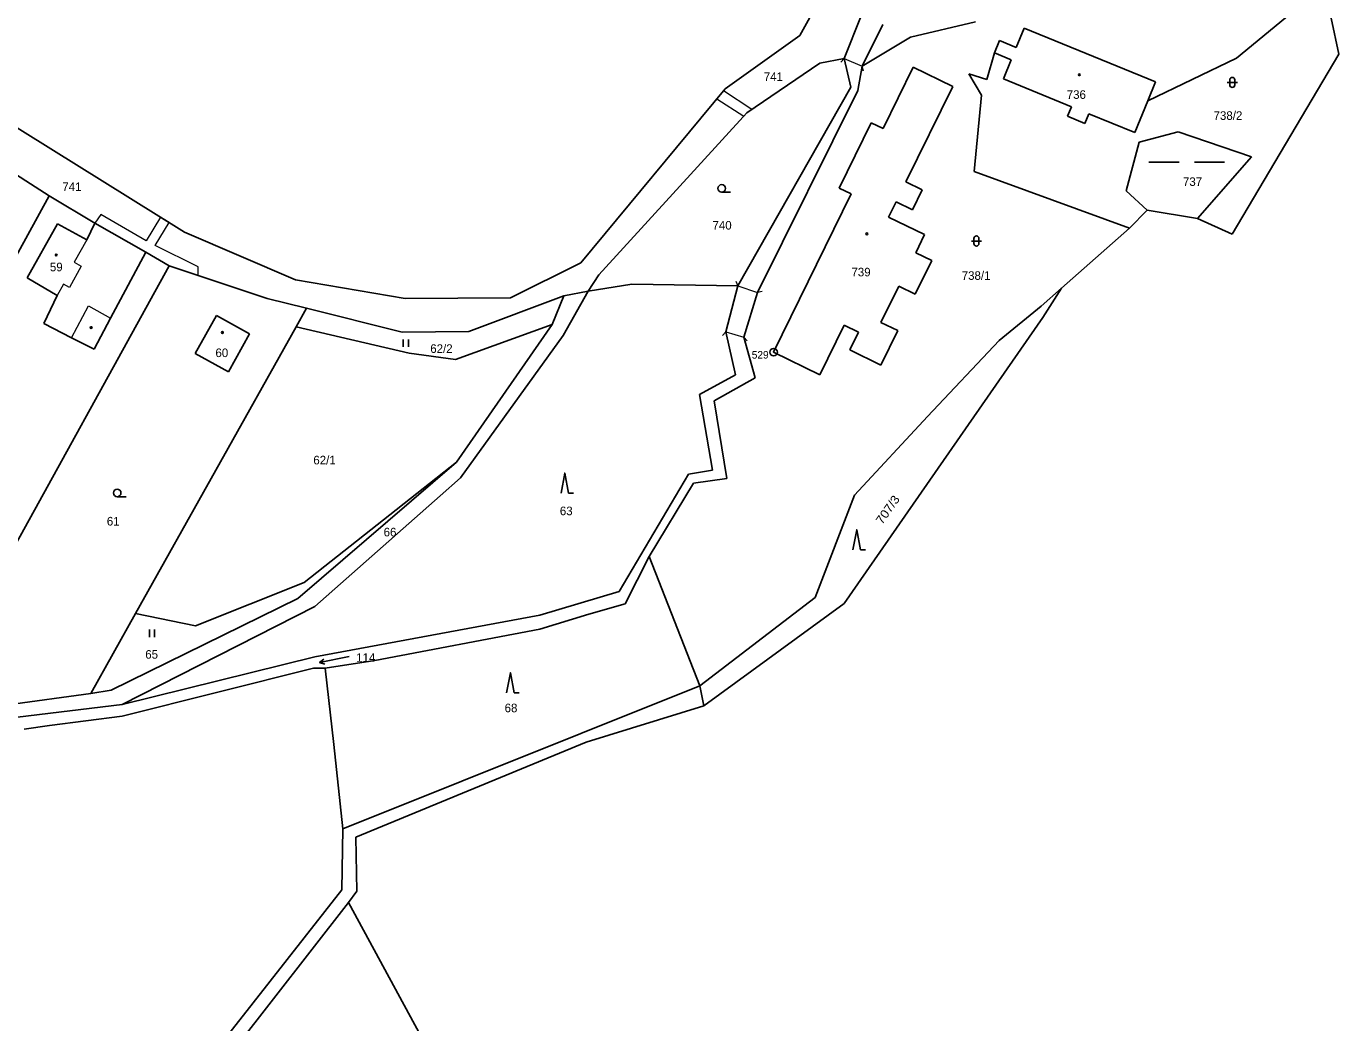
# Model space of a CAD drawing. Extents: x -727701 to -724405, y -960481 to -957284.
# Drawn here: x -726194 to -725934.2, y -958285.9 to -958088.6 of the extents above; entities that cross this region are included whole.
import ezdxf
from ezdxf.enums import TextEntityAlignment as Align

# ---------------------------------------------------------------- set-up
doc = ezdxf.new("R2010")
doc.units = 0
doc.header["$LTSCALE"] = 0.68
for name, color, linetype, lineweight in [('1', 7, 'Continuous', 25), ('13', 7, 'Continuous', 13), ('3', 7, 'Continuous', 25), ('4', 7, 'Continuous', 13), ('5', 7, 'Continuous', 25), ('8', 7, 'Continuous', 25)]:
    doc.layers.add(name, color=color, linetype=linetype, lineweight=lineweight)
doc.layers.add('2', color=7, linetype='Continuous')

msp = doc.modelspace()

# ---------------------------------------------------------------- linework, layer by layer
at = {"layer": '1'}
for p, q in [((-726036.81, -958083.12), (-726040.87, -958090.42)), ((-725942.48, -958085.07), (-725954.39, -958094.93)), ((-726028.71, -958086.53), (-726032.04, -958095.01)), ((-726006.06, -958087.73), (-726018.93, -958090.76)), ((-725935.63, -958086.98), (-725934.15, -958094.15)), ((-726024.39, -958088.24), (-726028.5, -958096.53)), ((-725997.99, -958092.81), (-725996.42, -958088.97)), ((-725996.42, -958088.97), (-725970.43, -958099.62)), ((-726040.87, -958090.42), (-726055.64, -958101.03)), ((-726018.93, -958090.76), (-726028.5, -958096.53)), ((-726002.27, -958093.89), (-726001.28, -958091.46)), ((-726001.28, -958091.46), (-725997.99, -958092.81)), ((-726032.04, -958095.01), (-726036.89, -958095.92)), ((-726032.04, -958095.01), (-726030.75, -958100.66)), ((-726002.27, -958093.89), (-726003.85, -958099.18)), ((-725998.99, -958095.24), (-726002.27, -958093.89)), ((-726000.53, -958099.02), (-725998.99, -958095.24)), ((-725954.39, -958094.93), (-725971.96, -958103.35)), ((-725934.15, -958094.15), (-725955.25, -958129.8)), ((-726036.89, -958095.92), (-726051.3, -958105.73)), ((-726028.5, -958096.53), (-726029.36, -958101.34)), ((-726024.36, -958108.87), (-726018.39, -958096.7)), ((-726018.39, -958096.7), (-726010.58, -958100.53)), ((-726003.85, -958099.18), (-726007.35, -958098.02)), ((-726007.35, -958098.02), (-726004.88, -958102.28)), ((-726030.75, -958100.66), (-726053.12, -958140)), ((-726010.58, -958100.53), (-726019.85, -958119.43)), ((-725987.05, -958104.54), (-726000.53, -958099.02)), ((-725970.43, -958099.62), (-725971.96, -958103.35)), ((-726206.6, -958101.98), (-726162.64, -958129.41)), ((-726055.64, -958101.03), (-726084.17, -958135.45)), ((-726029.36, -958101.34), (-726049.25, -958141.32)), ((-726004.88, -958102.28), (-726006.32, -958117.35)), ((-726051.3, -958105.73), (-726080.66, -958137.85)), ((-725987.82, -958106.43), (-725987.05, -958104.54)), ((-725983.61, -958105.93), (-725984.4, -958107.84)), ((-725974.54, -958109.65), (-725983.61, -958105.93)), ((-725971.96, -958103.35), (-725974.54, -958109.65)), ((-726212.67, -958107.28), (-726189.44, -958122.17)), ((-726033.04, -958120.65), (-726026.69, -958107.72)), ((-726026.69, -958107.72), (-726024.36, -958108.87)), ((-725984.4, -958107.84), (-725987.82, -958106.43)), ((-725973.63, -958111.53), (-725965.95, -958109.5)), ((-725965.95, -958109.5), (-725951.45, -958114.49)), ((-725976.24, -958121.22), (-725973.63, -958111.53)), ((-725951.45, -958114.49), (-725962.09, -958126.65)), ((-726006.32, -958117.35), (-725975.57, -958128.62)), ((-726030.7, -958121.79), (-726033.04, -958120.65)), ((-726019.85, -958119.43), (-726016.62, -958121.02)), ((-726016.62, -958121.02), (-726018.56, -958124.97)), ((-725972.05, -958125), (-725976.24, -958121.22)), ((-726189.44, -958122.17), (-726232.42, -958200.38)), ((-726189.44, -958122.17), (-726180.39, -958127.62)), ((-726046.03, -958153.14), (-726030.7, -958121.79)), ((-726021.79, -958123.38), (-726023.29, -958126.43)), ((-726018.56, -958124.97), (-726021.79, -958123.38)), ((-726023.29, -958126.43), (-726016.14, -958129.86)), ((-725972.05, -958125), (-725975.57, -958128.62)), ((-725962.09, -958126.65), (-725972.05, -958125)), ((-725955.25, -958129.8), (-725962.09, -958126.65)), ((-726193.78, -958138.44), (-726187.83, -958127.7)), ((-726187.83, -958127.7), (-726181.96, -958130.87)), ((-726181.96, -958130.87), (-726180.39, -958127.62)), ((-726180.39, -958127.62), (-726170.34, -958133.37)), ((-725975.57, -958128.62), (-725989.01, -958140.46)), ((-726140.67, -958138.85), (-726162.64, -958129.41)), ((-726016.14, -958129.86), (-726017.9, -958133.46)), ((-726177.3, -958146.43), (-726170.34, -958133.37)), ((-726170.34, -958133.37), (-726165.7, -958136.02)), ((-726017.9, -958133.46), (-726014.73, -958135.02)), ((-726165.7, -958136.02), (-726206.85, -958210.65)), ((-726165.7, -958136.02), (-726146.3, -958142.5)), ((-726084.17, -958135.45), (-726098.15, -958142.38)), ((-726014.73, -958135.02), (-726017.99, -958141.67)), ((-726118.97, -958142.54), (-726140.67, -958138.85)), ((-726080.66, -958137.85), (-726082.72, -958141.07)), ((-726082.72, -958141.07), (-726074.07, -958139.65)), ((-726053.12, -958140), (-726074.07, -958139.65)), ((-726106.38, -958149.08), (-726087.56, -958141.99)), ((-726089.89, -958147.63), (-726087.56, -958141.99)), ((-726082.72, -958141.07), (-726087.67, -958149.83)), ((-726087.56, -958141.99), (-726082.72, -958141.07)), ((-726053.12, -958140), (-726055.46, -958149.11)), ((-726049.25, -958141.32), (-726051.94, -958150.17)), ((-726021.26, -958140.06), (-726024.79, -958147.24)), ((-726017.99, -958141.67), (-726021.26, -958140.06)), ((-725989.01, -958140.46), (-725993.09, -958144.06)), ((-725992.76, -958146.28), (-725989.01, -958140.46)), ((-726146.3, -958142.5), (-726138.52, -958144.45)), ((-726140.58, -958148.13), (-726138.52, -958144.45)), ((-726138.52, -958144.45), (-726119.58, -958149.18)), ((-726098.15, -958142.38), (-726118.97, -958142.54)), ((-725993.09, -958144.06), (-726001.37, -958150.83)), ((-726190.53, -958147.44), (-726185.04, -958150.27)), ((-726180.57, -958152.56), (-726177.3, -958146.43)), ((-726160.52, -958153.38), (-726156.34, -958145.86)), ((-726156.34, -958145.86), (-726149.79, -958149.52)), ((-725992.76, -958146.28), (-726032.06, -958202.88)), ((-726024.79, -958147.24), (-726021.44, -958148.88)), ((-726172.34, -958204.88), (-726140.58, -958148.13)), ((-726149.79, -958149.52), (-726153.97, -958157.03)), ((-726140.58, -958148.13), (-726118.21, -958153.35)), ((-726119.58, -958149.18), (-726106.38, -958149.08)), ((-726109, -958154.58), (-726089.89, -958147.63)), ((-726108.8, -958174.9), (-726089.89, -958147.63)), ((-726087.67, -958149.83), (-726108, -958178)), ((-726053.6, -958157.6), (-726055.46, -958149.11)), ((-726032.09, -958147.77), (-726036.91, -958157.6)), ((-726029.21, -958149.18), (-726032.09, -958147.77)), ((-726030.93, -958152.68), (-726029.21, -958149.18)), ((-726021.44, -958148.88), (-726024.78, -958155.7)), ((-726185.04, -958150.27), (-726180.57, -958152.56)), ((-726051.94, -958150.17), (-726049.65, -958158.2)), ((-726024.78, -958155.7), (-726030.93, -958152.68)), ((-726001.37, -958150.83), (-726015.54, -958165.88)), ((-726153.97, -958157.03), (-726160.52, -958153.38)), ((-726118.21, -958153.35), (-726109, -958154.58)), ((-726036.91, -958157.6), (-726046.03, -958153.14)), ((-726060.7, -958161.55), (-726053.6, -958157.6)), ((-726049.65, -958158.2), (-726057.8, -958162.8)), ((-726058.12, -958176.52), (-726060.7, -958161.55)), ((-726057.8, -958162.8), (-726055.29, -958178.16)), ((-726015.54, -958165.88), (-726030.02, -958181.48)), ((-726140.2, -958201.9), (-726108.8, -958174.9)), ((-726138.99, -958198.75), (-726108.8, -958174.9)), ((-726108, -958178), (-726112.05, -958181.6)), ((-726076.6, -958200.5), (-726062.87, -958177.33)), ((-726062.87, -958177.33), (-726058.12, -958176.52)), ((-726055.29, -958178.16), (-726061.86, -958179.07)), ((-726061.86, -958179.07), (-726070.66, -958193.58)), ((-726112.05, -958181.6), (-726136.85, -958203.5)), ((-726030.02, -958181.48), (-726037.82, -958201.71)), ((-726070.66, -958193.58), (-726075.4, -958203)), ((-726070.66, -958193.58), (-726060.66, -958219.2)), ((-726160.5, -958207.3), (-726138.99, -958198.75)), ((-726177.2, -958220.1), (-726140.2, -958201.9)), ((-726092.3, -958205.2), (-726076.6, -958200.5)), ((-726037.82, -958201.71), (-726060.66, -958219.2)), ((-726136.85, -958203.5), (-726175, -958222.9)), ((-726075.4, -958203), (-726082.6, -958205)), ((-726059.85, -958223.18), (-726032.06, -958202.88)), ((-726181.2, -958220.7), (-726172.34, -958204.88)), ((-726172.34, -958204.88), (-726160.5, -958207.3)), ((-726136.85, -958213.5), (-726092.3, -958205.2)), ((-726082.6, -958205), (-726092.3, -958208)), ((-726092.3, -958208), (-726125, -958214.2)), ((-726175, -958222.9), (-726136.85, -958213.5)), ((-726125, -958214.2), (-726134.8, -958215.7)), ((-726137.1, -958215.7), (-726175, -958225.2)), ((-726134.8, -958215.7), (-726137.1, -958215.7)), ((-726133.1, -958230.8), (-726134.8, -958215.7)), ((-726181.2, -958220.7), (-726177.2, -958220.1)), ((-726131.32, -958247.51), (-726060.66, -958219.2)), ((-726060.66, -958219.2), (-726059.85, -958223.18)), ((-726197.6, -958223), (-726181.2, -958220.7)), ((-726195.7, -958225.4), (-726175, -958222.9)), ((-726175, -958225.2), (-726189.4, -958227.05)), ((-726083.14, -958230.39), (-726059.85, -958223.18)), ((-726189.4, -958227.05), (-726194.4, -958227.8)), ((-726128.76, -958249.16), (-726083.14, -958230.39)), ((-726131.32, -958247.51), (-726133.1, -958230.8)), ((-726131.48, -958259.62), (-726131.32, -958247.51)), ((-726128.53, -958259.86), (-726128.76, -958249.16)), ((-726156.53, -958291.46), (-726131.48, -958259.62)), ((-726130.22, -958262.09), (-726128.53, -958259.86)), ((-726130.22, -958262.09), (-726152.69, -958291.05)), ((-726107.42, -958304.01), (-726130.22, -958262.09))]:
    msp.add_line(p, q, dxfattribs=at)
msp.add_lwpolyline([(-726190.53, -958147.44), (-726187.88, -958141.93), (-726193.78, -958138.44)], dxfattribs=at)
at = {"layer": '13'}
for points in [[(-726057.24, -958102.96), (-726051.93, -958106.42), (-726051.3, -958105.73), (-726050.34, -958105.07), (-726055.96, -958101.41)], [(-726180.39, -958127.62), (-726170.34, -958133.37), (-726165.7, -958136.02), (-726159.98, -958137.93), (-726159.96, -958136.27), (-726168.48, -958132.04), (-726165.71, -958127.49), (-726167.41, -958126.44), (-726170.24, -958131.1), (-726179.2, -958125.88)]]:
    msp.add_lwpolyline(points, close=True, dxfattribs=at)
at = {"layer": '3'}
for p, q in [((-725956.221, -958099.731), (-725954.219, -958099.731)), ((-725955.721, -958099.231), (-725955.721, -958100.232)), ((-725954.719, -958100.232), (-725954.719, -958099.231)), ((-725971.739, -958115.51), (-725965.739, -958115.51)), ((-725962.739, -958115.51), (-725956.739, -958115.51)), ((-726056.303, -958121.46), (-726054.553, -958121.46)), ((-726006.881, -958131.131), (-726004.879, -958131.131)), ((-726006.381, -958130.631), (-726006.381, -958131.632)), ((-726005.379, -958131.632), (-726005.379, -958130.631)), ((-726119.341, -958152.1), (-726119.341, -958150.6)), ((-726118.34, -958152.1), (-726118.34, -958150.6)), ((-726086.62, -958181.08), (-726085.624, -958181.08)), ((-726175.983, -958181.77), (-726174.233, -958181.77)), ((-726028.83, -958192.29), (-726027.834, -958192.29)), ((-726169.571, -958209.55), (-726169.571, -958208.05)), ((-726168.57, -958209.55), (-726168.57, -958208.05)), ((-726135.903, -958214.619), (-726135.051, -958213.925)), ((-726097.4, -958220.62), (-726096.404, -958220.62))]:
    msp.add_line(p, q, dxfattribs=at)
for points in [[(-726086.62, -958181.08), (-726087.37, -958177.08), (-726088.12, -958181.08)], [(-726028.83, -958192.29), (-726029.58, -958188.29), (-726030.33, -958192.29)], [(-726130.034, -958213.371), (-726135.903, -958214.619), (-726134.843, -958214.906)], [(-726097.4, -958220.62), (-726098.15, -958216.62), (-726098.9, -958220.62)]]:
    msp.add_lwpolyline(points, dxfattribs=at)
for centre in [(-726056.3029, -958120.7098), (-726175.9829, -958181.0198)]:
    msp.add_circle(centre, 0.75, dxfattribs=at)
for centre, start, end in [((-725955.22, -958099.2309), 0, 180), ((-725955.22, -958100.2309), 180, 359.98789), ((-726005.88, -958130.6309), 0, 180), ((-726005.88, -958131.6309), 180, 359.98789)]:
    msp.add_arc(centre, 0.5, start, end, dxfattribs=at)
at = {"layer": '4'}
for p, q in [((-726032.748, -958095.717), (-726032.041, -958095.01)), ((-726032.04, -958095.01), (-726028.5, -958096.53)), ((-726028.242, -958097.496), (-726028.5, -958096.531)), ((-726181.96, -958130.87), (-726184.52, -958135.31)), ((-726183.14, -958136.14), (-726185.44, -958140.32)), ((-726184.52, -958135.31), (-726183.14, -958136.14)), ((-726186.64, -958139.67), (-726187.88, -958141.93)), ((-726185.44, -958140.32), (-726186.64, -958139.67)), ((-726053.494, -958139.072), (-726053.12, -958139.999)), ((-726053.12, -958140), (-726049.25, -958141.32)), ((-726048.271, -958141.113), (-726049.249, -958141.32)), ((-726185.04, -958150.27), (-726181.69, -958143.99)), ((-726181.69, -958143.99), (-726177.3, -958146.43)), ((-726056.168, -958149.817), (-726055.461, -958149.11)), ((-726055.46, -958149.11), (-726051.94, -958150.17)), ((-726051.284, -958150.925), (-726051.94, -958150.171))]:
    msp.add_line(p, q, dxfattribs=at)
at = {"layer": '5'}
for centre in [(-725985.5068, -958098.2092), (-726027.5668, -958129.7092), (-726188.0468, -958133.9092), (-726181.1368, -958148.2792), (-726155.1568, -958149.2392)]:
    msp.add_circle(centre, 0.175, dxfattribs=at)
at = {"layer": '8'}
for radius in [0.75, 0.03]:
    msp.add_circle((-726046.03, -958153.1398), radius, dxfattribs=at)

# ---------------------------------------------------------------- texts
at = {"layer": '2'}
for s, p in [('741', (-726047.97, -958099.435)), ('736', (-725988, -958102.985)), ('738/2', (-725958.93, -958107.145)), ('737', (-725964.99, -958120.225)), ('741', (-726186.85, -958121.235)), ('740', (-726058.13, -958128.865)), ('739', (-726030.62, -958138.135)), ('738/1', (-726008.79, -958138.825)), ('60', (-726156.53, -958154.115)), ('62/2', (-726114, -958153.285)), ('62/1', (-726137.15, -958175.365)), ('63', (-726088.35, -958185.425)), ('61', (-726178.03, -958187.465)), ('66', (-726123.23, -958189.615)), ('65', (-726170.42, -958213.835)), ('114', (-726128.66, -958214.455)), ('68', (-726099.28, -958224.445))]:
    msp.add_text(s, height=1.7, dxfattribs=at).set_placement(p)
msp.add_text('59', height=1.7, dxfattribs=at).set_placement((-726188.039, -958137.125), align=Align.CENTER)
at = {"layer": '2', "width": 1.1}
msp.add_text('707/3', height=1.7, rotation=55, dxfattribs=at).set_placement((-726024.541, -958187.383))
at = {"layer": '8'}
msp.add_text('529', height=1.5, dxfattribs=at).set_placement((-726050.36, -958154.415))

doc.saveas('drawing.dxf')
